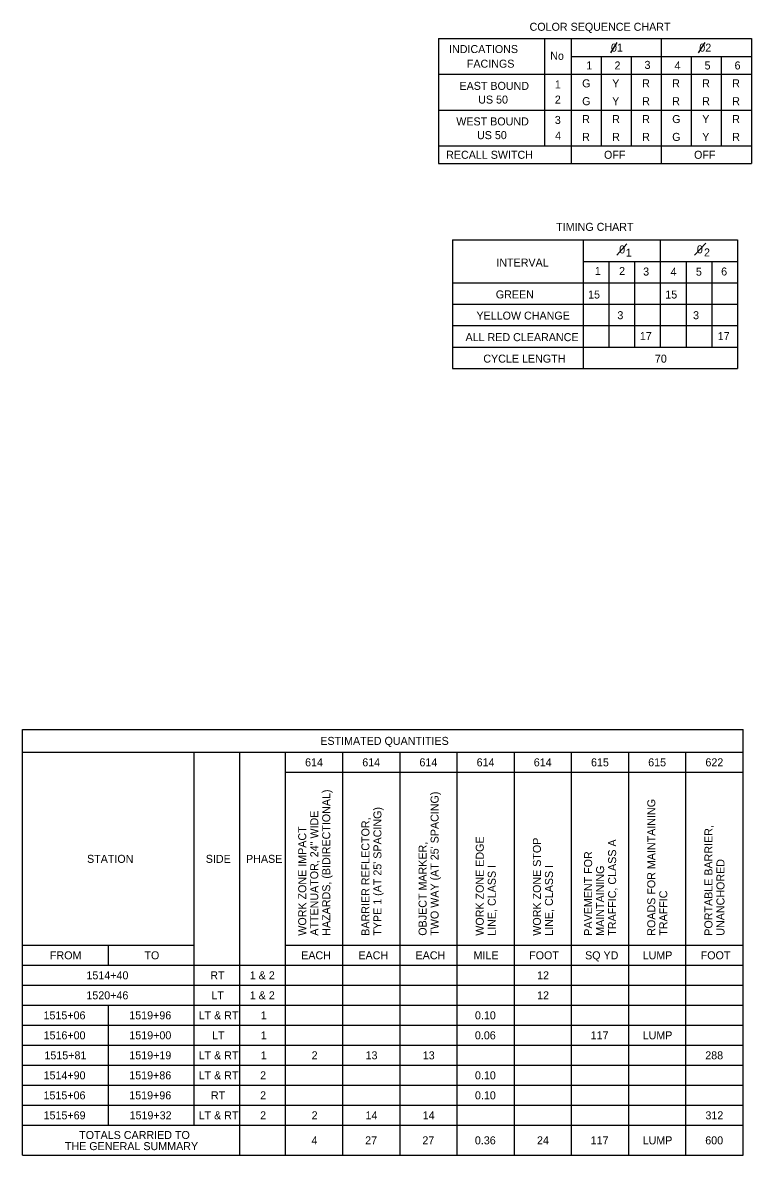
# Model space of a CAD drawing. Extents: x 0 to 74, y -29.1 to 22.
# Drawn here: x 47.13 to 59.87, y -1.6 to 18.23 of the extents above; entities that cross this region are included whole.
import ezdxf

# ---------------------------------------------------------------- set-up
doc = ezdxf.new("R2010")
doc.units = 0
for name, color, linetype in [('Default', 7, 'Continuous'), ('SH_Text', 7, 'Continuous'), ('TX_P_1', 7, 'Continuous')]:
    doc.layers.add(name, color=color, linetype=linetype)

msp = doc.modelspace()

# ---------------------------------------------------------------- linework, layer by layer
at = {"layer": 'Default'}
for p, q in [((54.406, 17.946), (54.406, 15.758)), ((54.406, 17.946), (59.875, 17.946)), ((56.256, 17.946), (56.256, 16.071)), ((56.725, 17.946), (56.725, 15.758)), ((58.3, 17.946), (58.3, 15.758)), ((59.875, 17.946), (59.875, 15.758)), ((59.875, 17.946), (59.875, 15.758)), ((56.725, 17.633), (59.875, 17.633)), ((57.25, 17.633), (57.25, 16.071)), ((57.775, 17.633), (57.775, 16.071)), ((58.825, 17.633), (58.825, 16.071)), ((59.35, 17.633), (59.35, 16.071)), ((54.406, 17.321), (59.875, 17.321)), ((54.406, 16.696), (59.875, 16.696)), ((54.406, 16.071), (59.875, 16.071)), ((54.406, 15.758), (59.875, 15.758)), ((54.647, 14.423), (59.633, 14.423)), ((54.647, 14.423), (54.647, 12.173)), ((56.933, 14.423), (56.933, 12.173)), ((58.283, 14.423), (58.283, 12.548)), ((59.633, 14.423), (59.633, 12.173)), ((56.933, 14.048), (59.633, 14.048)), ((57.383, 14.048), (57.383, 12.548)), ((57.833, 14.048), (57.833, 12.548)), ((58.733, 14.048), (58.733, 12.548)), ((59.183, 14.048), (59.183, 12.548)), ((54.647, 13.673), (59.633, 13.673)), ((54.647, 13.298), (59.633, 13.298)), ((54.647, 12.923), (59.633, 12.923)), ((54.647, 12.548), (59.633, 12.548)), ((54.647, 12.173), (59.633, 12.173))]:
    msp.add_line(p, q, dxfattribs=at)
at = {"layer": 'SH_Text'}
for p, q in [((47.13, -1.595), (47.13, 5.857)), ((47.13, 5.857), (59.73, 5.857)), ((59.73, -1.595), (59.73, 5.857)), ((47.13, 5.457), (59.73, 5.457)), ((50.13, -1.07), (50.13, 5.457)), ((50.93, -1.595), (50.93, 5.457)), ((51.73, -1.595), (51.73, 5.457)), ((52.73, -1.595), (52.73, 5.457)), ((53.73, -1.595), (53.73, 5.457)), ((54.73, -1.595), (54.73, 5.457)), ((55.73, -1.595), (55.73, 5.457)), ((56.73, -1.595), (56.73, 5.457)), ((57.73, -1.595), (57.73, 5.457)), ((58.73, -1.595), (58.73, 5.457)), ((51.73, 5.107), (59.73, 5.107)), ((47.13, 2.08), (50.13, 2.08)), ((48.63, 1.73), (48.63, 2.08)), ((51.73, 2.08), (59.73, 2.08)), ((47.13, 1.73), (59.73, 1.73)), ((47.13, 1.38), (59.73, 1.38)), ((47.13, 1.03), (59.73, 1.03)), ((48.63, -1.07), (48.63, 1.03)), ((47.13, 0.68), (59.73, 0.68)), ((47.13, 0.33), (59.73, 0.33)), ((47.13, -0.02), (59.73, -0.02)), ((47.13, -0.37), (59.73, -0.37)), ((47.13, -0.72), (59.73, -0.72)), ((47.13, -1.07), (59.73, -1.07)), ((47.13, -1.595), (59.73, -1.595))]:
    msp.add_line(p, q, dxfattribs=at)
at = {"layer": 'TX_P_1'}
for p, q in [((57.415, 17.698), (57.531, 17.879)), ((58.953, 17.698), (59.068, 17.879)), ((57.522, 14.154), (57.699, 14.355)), ((58.879, 14.155), (59.079, 14.365))]:
    msp.add_line(p, q, dxfattribs=at)

# ---------------------------------------------------------------- texts
at = {"layer": 'Default'}
for s, p in [('COLOR SEQUENCE CHART', (55.996, 18.083)), ('TIMING CHART', (56.462, 14.582))]:
    msp.add_text(s, height=0.14, dxfattribs=at).set_placement(p)
at = {"layer": 'SH_Text'}
for s, p in [('ESTIMATED QUANTITIES', (52.336, 5.587)), ('614', (52.07, 5.212)), ('614', (53.07, 5.212)), ('614', (54.07, 5.212)), ('614', (55.07, 5.212)), ('614', (56.07, 5.212)), ('615', (57.071, 5.212)), ('615', (58.071, 5.212)), ('622', (59.072, 5.212)), ('STATION', (48.256, 3.523)), ('SIDE', (50.333, 3.523)), ('PHASE', (51.037, 3.523)), ('FROM', (47.607, 1.835)), ('TO', (49.26, 1.835)), ('EACH', (52.002, 1.835)), ('EACH', (53.002, 1.835)), ('EACH', (54.002, 1.835)), ('MILE', (55.016, 1.835)), ('FOOT', (55.989, 1.835)), ('SQ YD', (56.967, 1.835)), ('LUMP', (57.974, 1.835)), ('FOOT', (58.989, 1.835)), ('1514+40', (48.246, 1.485)), ('RT', (50.412, 1.485)), ('1 & 2', (51.103, 1.485)), ('12', (56.128, 1.485)), ('1520+46', (48.245, 1.135)), ('LT', (50.431, 1.135)), ('1 & 2', (51.103, 1.135)), ('12', (56.128, 1.135)), ('1515+06', (47.495, 0.785)), ('1519+96', (48.995, 0.785)), ('LT & RT', (50.208, 0.785)), ('1', (51.295, 0.785)), ('0.10', (55.041, 0.785)), ('1516+00', (47.496, 0.435)), ('1519+00', (48.996, 0.435)), ('LT', (50.443, 0.435)), ('1', (51.295, 0.435)), ('0.06', (55.04, 0.435)), ('117', (57.065, 0.435)), ('LUMP', (57.974, 0.435)), ('1515+81', (47.511, 0.085)), ('1519+19', (48.996, 0.085)), ('LT & RT', (50.208, 0.085)), ('1', (51.295, 0.085)), ('2', (52.184, 0.085)), ('13', (53.128, 0.085)), ('13', (54.128, 0.085)), ('288', (59.069, 0.085)), ('1514+90', (47.496, -0.265)), ('1519+86', (48.995, -0.265)), ('LT & RT', (50.208, -0.265)), ('2', (51.284, -0.265)), ('0.10', (55.041, -0.265)), ('1515+06', (47.495, -0.615)), ('1519+96', (48.995, -0.615)), ('RT', (50.423, -0.615)), ('2', (51.284, -0.615)), ('0.10', (55.041, -0.615)), ('1515+69', (47.496, -0.965)), ('1519+32', (49, -0.965)), ('LT & RT', (50.208, -0.965)), ('2', (51.284, -0.965)), ('2', (52.184, -0.965)), ('14', (53.127, -0.965)), ('14', (54.127, -0.965)), ('312', (59.072, -0.965)), ('TOTALS CARRIED TO', (48.119, -1.309)), ('THE GENERAL SUMMARY', (47.869, -1.504)), ('4', (52.182, -1.403)), ('27', (53.121, -1.403)), ('27', (54.121, -1.403)), ('0.36', (55.04, -1.403)), ('24', (56.126, -1.403)), ('117', (57.065, -1.403)), ('LUMP', (57.974, -1.403)), ('600', (59.069, -1.403))]:
    msp.add_text(s, height=0.14, dxfattribs=at).set_placement(p)
for s, p in [('HAZARDS, (BIDIRECTIONAL)', (52.51, 2.248)), ("TWO WAY (AT 25' SPACING)", (54.405, 2.248)), ('ROADS FOR MAINTAINING', (58.195, 2.248)), ('ATTENUATOR, 24" WIDE', (52.3, 2.248)), ("TYPE 1 (AT 25' SPACING)", (53.405, 2.248)), ('BARRIER REFLECTOR,', (53.195, 2.248)), ('PORTABLE BARRIER,', (59.195, 2.248)), ('WORK ZONE IMPACT', (52.09, 2.248)), ('WORK ZONE EDGE', (55.195, 2.248)), ('OBJECT MARKER,', (54.195, 2.248)), ('WORK ZONE STOP', (56.195, 2.248)), ('TRAFFIC, CLASS A', (57.51, 2.248)), ('PAVEMENT FOR', (57.09, 2.248)), ('UNANCHORED', (59.405, 2.248)), ('LINE, CLASS I', (55.405, 2.248)), ('LINE, CLASS I', (56.405, 2.248)), ('MAINTAINING', (57.3, 2.248)), ('TRAFFIC', (58.405, 2.248))]:
    msp.add_text(s, height=0.14, rotation=90, dxfattribs=at).set_placement(p)
at = {"layer": 'TX_P_1'}
for s, p in [('01', (57.42, 17.718)), ('02', (58.965, 17.718)), ('INDICATIONS', (54.588, 17.693)), ('No', (56.358, 17.575)), ('FACINGS', (54.899, 17.437)), ('1', (56.987, 17.406)), ('2', (57.482, 17.406)), ('3', (58.007, 17.416)), ('4', (58.532, 17.406)), ('5', (59.057, 17.406)), ('6', (59.582, 17.406)), ('EAST BOUND', (54.77, 17.049)), ('1', (56.438, 17.074)), ('G', (56.916, 17.093)), ('Y', (57.441, 17.093)), ('R', (57.966, 17.093)), ('R', (58.491, 17.093)), ('R', (59.016, 17.093)), ('R', (59.541, 17.093)), ('US 50', (55.098, 16.809)), ('2', (56.438, 16.809)), ('G', (56.916, 16.781)), ('Y', (57.441, 16.781)), ('R', (57.966, 16.781)), ('R', (58.491, 16.781)), ('R', (59.016, 16.781)), ('R', (59.541, 16.781)), ('WEST BOUND', (54.714, 16.427)), ('3', (56.438, 16.453)), ('R', (56.916, 16.468)), ('R', (57.441, 16.468)), ('R', (57.966, 16.468)), ('G', (58.491, 16.468)), ('Y', (59.016, 16.468)), ('R', (59.541, 16.468)), ('US 50', (55.077, 16.187)), ('4', (56.443, 16.18)), ('R', (56.916, 16.156)), ('R', (57.441, 16.156)), ('R', (57.966, 16.156)), ('G', (58.491, 16.156)), ('Y', (59.016, 16.156)), ('R', (59.541, 16.156)), ('RECALL SWITCH', (54.537, 15.843)), ('OFF', (57.298, 15.843)), ('OFF', (58.873, 15.843)), ('0', (57.564, 14.187)), ('0', (58.923, 14.189)), ('2', (59.047, 14.134)), ('INTERVAL ', (55.415, 13.958)), ('1', (57.679, 14.131)), ('1', (57.138, 13.811)), ('2', (57.562, 13.809)), ('3', (57.983, 13.8)), ('4', (58.462, 13.796)), ('5', (58.905, 13.798)), ('6', (59.347, 13.801)), (' GREEN', (55.354, 13.4)), ('15', (57.02, 13.398)), ('15', (58.37, 13.398)), ('YELLOW CHANGE', (55.067, 13.029)), ('3', (57.532, 13.036)), ('3', (58.856, 13.036)), ('ALL RED CLEARANCE', (54.876, 12.652)), ('17', (57.925, 12.671)), ('17', (59.287, 12.671)), ('CYCLE LENGTH', (55.187, 12.276)), ('70', (58.188, 12.276))]:
    msp.add_text(s, height=0.14, dxfattribs=at).set_placement(p)

doc.saveas('drawing.dxf')
